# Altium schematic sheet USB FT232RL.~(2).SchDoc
size A4
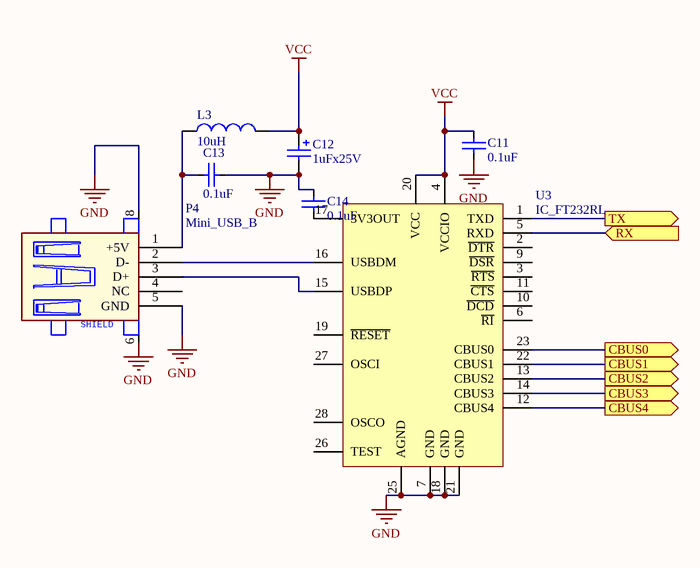
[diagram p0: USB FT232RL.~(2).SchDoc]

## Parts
C11  0.1uF  [LINO/CPP27RM10MMX20MMX31MM]
C12  1uFx25V  [CaseC_EIA6032]
C13  0.1uF  [LINO/CPP27RM10MMX20MMX31MM]
C14  0.1uF  [LINO/CPP27RM10MMX20MMX31MM]
L3  10uH  [LL0603\2P]
P4  Mini_USB_B  [4UCON_MINI_USB-B]
U3  IC_FT232RL  [SSOP-28]

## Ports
CBUS0 (out), CBUS1 (out), CBUS2 (out), CBUS3 (out), CBUS4 (out), RX (in), TX (out)

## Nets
GND: C11.2 C12.2 C13.2 C14.1 P4.5(GND) P4.6(GND) P4.8(GND) U3.7(GND) U3.18(GND) U3.21(GND) U3.25(AGND)
NC: U3.8(NC) U3.24(NC)
VCC: C11.1 C12.1 L3.2 U3.4(VCCIO) U3.20(VCC)
CBUS0: U3.23(CBUS0) ; port CBUS0
CBUS1: U3.22(CBUS1) ; port CBUS1
CBUS2: U3.13(CBUS2) ; port CBUS2
CBUS3: U3.14(CBUS3) ; port CBUS3
CBUS4: U3.12(CBUS4) ; port CBUS4
RX: U3.5(RXD) ; port RX
TX: U3.1(TXD) ; port TX
NetC13_1: C13.1 L3.1 P4.1(+5V)
NetC14_2: C14.2 U3.17(3V3OUT)
NetP4_2: P4.2(D-) U3.16(USBDM)
NetP4_3: P4.3(D+) U3.15(USBDP)

Not connected (* = marked no-connect by the designer): P4 4(NC); U3 2(~{DTR}) 3(~{RTS}) 6(~{RI}) 9(~{DSR}) 10(~{DCD}) 11(~{CTS}) 19(~{RESET}) 26(TEST) 27(OSCI) 28(OSCO)

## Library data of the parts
C11 C13 C14 = Cap_Cer: Capacitor ceramic
C12 = Cap_Tan: Tantal capacitor
L3 = Inductor
U3 = IC_FT232RL: FT232R USB UART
